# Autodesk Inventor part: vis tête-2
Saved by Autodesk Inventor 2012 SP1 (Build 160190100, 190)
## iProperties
Created: 2014-12
Part Number: vis tête-2
Material: Default
Document SubType Name: Modeling
Designer: Bruno
Density: 1 g/cm^3
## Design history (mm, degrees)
node "vis tête-21"
node "vis tête-2"
node "Base1"
